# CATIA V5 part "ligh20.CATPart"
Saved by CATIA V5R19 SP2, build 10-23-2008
Part number: ligh20
Bounding box of the stored display mesh (mm): x 1643.774 to 1735.768, y -530.071 to 530.071, z 411.73 to 459.236
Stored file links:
  C:\BEHROOZ\catia learning\tarh haye mashin\hb\ligh20.CATPart
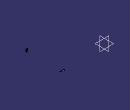
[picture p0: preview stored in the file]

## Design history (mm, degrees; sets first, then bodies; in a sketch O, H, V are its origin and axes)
Body1 (main body)
  DatumSurface1
  ThickSurface1: Surface DatumSurface1, TopOffset 25, BotOffset -10
  Symmetry1: ToTransfor DatumSurface1, Reference zx-plane
  ThickSurface2: Surface Symmetry1, TopOffset 25, BotOffset -10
